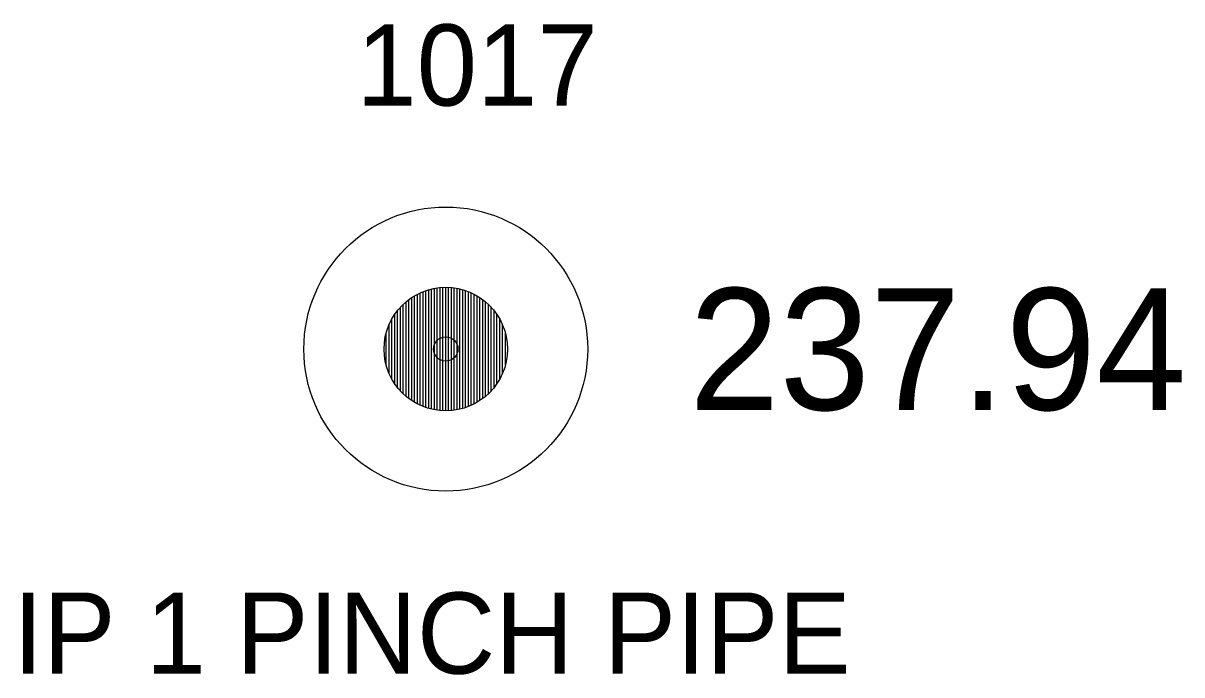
# Model space of a CAD drawing. Extents: x 1961231 to 1962574, y 799865 to 801120.
# Drawn here: x 1962039.98 to 1962054.27, y 800175.22 to 800183.25 of the extents above; entities that cross this region are included whole.
import ezdxf

# ---------------------------------------------------------------- set-up
doc = ezdxf.new("R2010")
doc.units = 0
for name, color, linetype in [('RD_EX_DV_Prop_txCode', 7, 'Continuous'), ('RD_EX_DV_PropPin', 7, 'Continuous'), ('RD_EX_TX_DV_Prop_ELEV', 7, 'Continuous'), ('RD_SMD_Locator', 7, 'Continuous')]:
    doc.layers.add(name, color=color, linetype=linetype)

msp = doc.modelspace()

# ---------------------------------------------------------------- linework, layer by layer
at = {"layer": 'RD_EX_DV_PropPin'}
for p, q in [((1962044.769, 800178.604), (1962044.769, 800179.873)), ((1962044.804, 800178.582), (1962044.804, 800179.895)), ((1962044.839, 800178.563), (1962044.839, 800179.914)), ((1962044.874, 800178.546), (1962044.874, 800179.931)), ((1962044.909, 800178.531), (1962044.909, 800179.946)), ((1962044.944, 800178.518), (1962044.944, 800179.959)), ((1962044.979, 800178.507), (1962044.979, 800179.97)), ((1962045.014, 800178.498), (1962045.014, 800179.979)), ((1962045.049, 800178.49), (1962045.049, 800179.986)), ((1962045.084, 800178.485), (1962045.084, 800179.992)), ((1962045.119, 800178.481), (1962045.119, 800179.996)), ((1962045.154, 800178.478), (1962045.154, 800179.999)), ((1962045.189, 800178.477), (1962045.189, 800179.999)), ((1962045.224, 800178.478), (1962045.224, 800179.999)), ((1962045.259, 800178.481), (1962045.259, 800179.996)), ((1962045.294, 800178.485), (1962045.294, 800179.992)), ((1962045.329, 800178.49), (1962045.329, 800179.986)), ((1962045.364, 800178.498), (1962045.364, 800179.979)), ((1962045.399, 800178.507), (1962045.399, 800179.97)), ((1962045.434, 800178.518), (1962045.434, 800179.959)), ((1962045.469, 800178.531), (1962045.469, 800179.946)), ((1962045.504, 800178.546), (1962045.504, 800179.931)), ((1962045.539, 800178.563), (1962045.539, 800179.914)), ((1962045.574, 800178.582), (1962045.574, 800179.895)), ((1962045.609, 800178.604), (1962045.609, 800179.873)), ((1962044.629, 800178.723), (1962044.629, 800179.753)), ((1962044.664, 800178.688), (1962044.664, 800179.789)), ((1962044.699, 800178.656), (1962044.699, 800179.82)), ((1962044.734, 800178.628), (1962044.734, 800179.848)), ((1962045.644, 800178.628), (1962045.644, 800179.848)), ((1962045.679, 800178.656), (1962045.679, 800179.82)), ((1962045.714, 800178.688), (1962045.714, 800179.789)), ((1962045.749, 800178.723), (1962045.749, 800179.753)), ((1962044.524, 800178.869), (1962044.524, 800179.608)), ((1962044.559, 800178.812), (1962044.559, 800179.665)), ((1962044.594, 800178.764), (1962044.594, 800179.712)), ((1962045.784, 800178.764), (1962045.784, 800179.712)), ((1962045.819, 800178.812), (1962045.819, 800179.665)), ((1962045.854, 800178.869), (1962045.854, 800179.608)), ((1962044.489, 800178.94), (1962044.489, 800179.536)), ((1962045.889, 800178.94), (1962045.889, 800179.536)), ((1962044.454, 800179.042), (1962044.454, 800179.434)), ((1962045.924, 800179.042), (1962045.924, 800179.434))]:
    msp.add_line(p, q, dxfattribs=at)
for radius in [1.75, 0.761]:
    msp.add_circle((1962045.189, 800179.238), radius, dxfattribs=at)
at = {"layer": 'RD_SMD_Locator'}
msp.add_circle((1962045.189, 800179.238), 0.15, dxfattribs=at)

# ---------------------------------------------------------------- texts
at = {"layer": 'RD_EX_DV_Prop_txCode'}
for s, p in [('1017', (1962044.087, 800182.238)), ('IP 1 PINCH PIPE', (1962039.854, 800175.238))]:
    msp.add_text(s, height=1, dxfattribs=at).set_placement(p)
at = {"layer": 'RD_EX_TX_DV_Prop_ELEV'}
msp.add_text('237.94', height=1.5, dxfattribs=at).set_placement((1962048.189, 800178.488))

doc.saveas('drawing.dxf')
